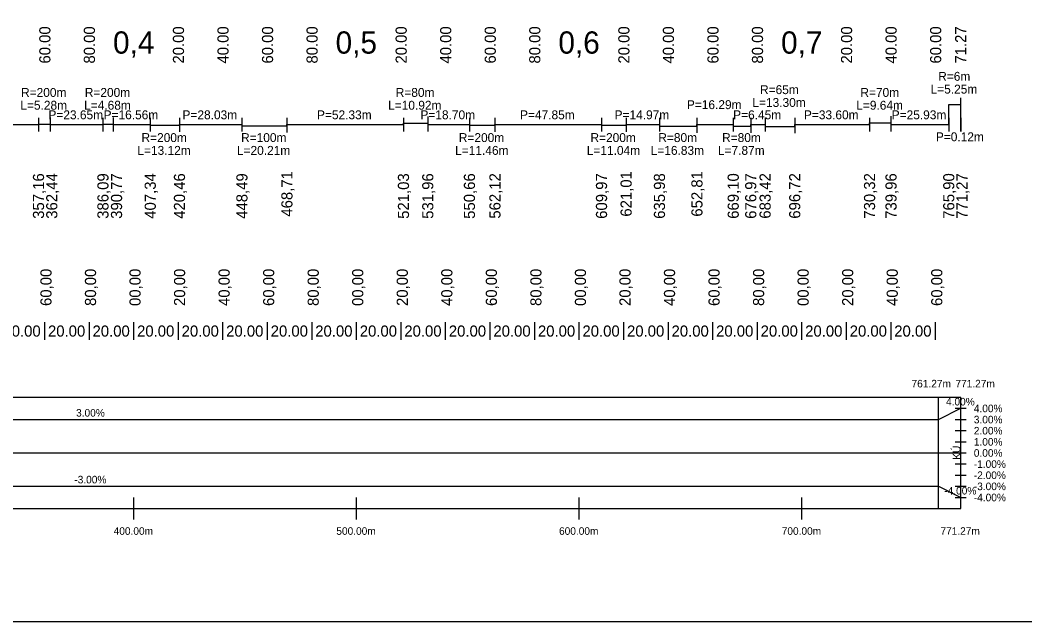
# Model space of a CAD drawing. Extents: x -603528 to -602138, y -1111983 to -1111218.
# Drawn here: x -603007.2 to -602556, y -1111982.7 to -1111712.4 of the extents above; entities that cross this region are included whole.
import ezdxf

# ---------------------------------------------------------------- set-up
doc = ezdxf.new("R2010")
doc.units = 0
for name, color, linetype in [('_křivky z hran', 7, 'Continuous'), ('_netisk', 7, 'Continuous'), ('C3D_Klopeni', 7, 'Continuous'), ('C3D_ZPP', 7, 'Continuous'), ('C3D_ZPP-Prouzky', 7, 'Continuous'), ('Default', 7, 'Continuous')]:
    doc.layers.add(name, color=color, linetype=linetype)

# ---------------------------------------------------------------- blocks, each defined once
blk = doc.blocks.new('AeccTickLine')
at = {"layer": 'Default'}
blk.add_line((0, 1), (0, -1), dxfattribs=at)

msp = doc.modelspace()

# ---------------------------------------------------------------- linework, layer by layer
at = {"layer": '_netisk'}
msp.add_lwpolyline([(-603527.56, -1111262.74), (-602137.56, -1111262.74), (-602137.56, -1111982.74), (-603527.56, -1111982.74)], close=True, dxfattribs=at)
at = {"layer": 'C3D_Klopeni'}
for p, q in [((-603356.07, -1111881.8), (-602584.81, -1111881.8)), ((-602594.8, -1111931.8), (-602594.8, -1111881.8)), ((-602584.81, -1111931.8), (-602584.81, -1111881.8)), ((-602584.81, -1111931.8), (-602584.81, -1111881.8)), ((-602594.8, -1111891.8), (-602584.81, -1111886.8)), ((-602587.31, -1111886.8), (-602582.31, -1111886.8)), ((-603356.07, -1111891.8), (-602594.8, -1111891.8)), ((-602587.31, -1111891.8), (-602582.31, -1111891.8)), ((-602587.31, -1111896.8), (-602582.31, -1111896.8)), ((-602587.31, -1111901.8), (-602582.31, -1111901.8)), ((-603356.07, -1111906.8), (-602584.81, -1111906.8)), ((-602587.31, -1111906.8), (-602582.31, -1111906.8)), ((-602587.31, -1111911.8), (-602582.31, -1111911.8)), ((-602587.31, -1111916.8), (-602582.31, -1111916.8)), ((-603356.07, -1111921.8), (-602594.8, -1111921.8)), ((-602594.8, -1111921.8), (-602584.81, -1111926.8)), ((-602587.31, -1111921.8), (-602582.31, -1111921.8)), ((-602956.07, -1111936.8), (-602956.07, -1111926.8)), ((-602856.07, -1111936.8), (-602856.07, -1111926.8)), ((-602756.07, -1111936.8), (-602756.07, -1111926.8)), ((-602656.07, -1111936.8), (-602656.07, -1111926.8)), ((-602587.31, -1111926.8), (-602582.31, -1111926.8)), ((-603356.07, -1111931.8), (-602584.81, -1111931.8))]:
    msp.add_line(p, q, dxfattribs=at)
at = {"layer": 'C3D_ZPP'}
for p, q in [((-602590.18, -1111759.4), (-602590.18, -1111750.4)), ((-602590.18, -1111750.4), (-602584.92, -1111750.4)), ((-602584.92, -1111750.4), (-602584.92, -1111759.4)), ((-603040.03, -1111759.4), (-602998.92, -1111759.4)), ((-602998.92, -1111759.4), (-602998.92, -1111759.13)), ((-602998.92, -1111759.13), (-602993.64, -1111759.13)), ((-602993.64, -1111759.13), (-602993.64, -1111759.4)), ((-602993.64, -1111759.4), (-602969.98, -1111759.4)), ((-602969.98, -1111759.4), (-602969.98, -1111759.13)), ((-602969.98, -1111759.13), (-602965.3, -1111759.13)), ((-602965.3, -1111759.13), (-602965.3, -1111759.4)), ((-602965.3, -1111759.4), (-602948.74, -1111759.4)), ((-602948.74, -1111759.4), (-602948.74, -1111759.67)), ((-602948.74, -1111759.67), (-602935.62, -1111759.67)), ((-602935.62, -1111759.67), (-602935.62, -1111759.4)), ((-602935.62, -1111759.4), (-602907.58, -1111759.4)), ((-602907.58, -1111759.4), (-602907.58, -1111759.94)), ((-602907.58, -1111759.94), (-602887.37, -1111759.94)), ((-602887.37, -1111759.94), (-602887.37, -1111759.4)), ((-602887.37, -1111759.4), (-602835.04, -1111759.4)), ((-602835.04, -1111759.4), (-602835.04, -1111758.72)), ((-602835.04, -1111758.72), (-602824.12, -1111758.72)), ((-602824.12, -1111758.72), (-602824.12, -1111759.4)), ((-602824.12, -1111759.4), (-602805.42, -1111759.4)), ((-602805.42, -1111759.4), (-602805.42, -1111759.67)), ((-602805.42, -1111759.67), (-602793.96, -1111759.67)), ((-602793.96, -1111759.67), (-602793.96, -1111759.4)), ((-602793.96, -1111759.4), (-602746.1, -1111759.4)), ((-602746.1, -1111759.4), (-602746.1, -1111759.67)), ((-602746.1, -1111759.67), (-602735.06, -1111759.67)), ((-602735.06, -1111759.67), (-602735.06, -1111759.4)), ((-602735.06, -1111759.4), (-602720.09, -1111759.4)), ((-602720.09, -1111759.4), (-602720.09, -1111760.07)), ((-602720.09, -1111760.07), (-602703.26, -1111760.07)), ((-602703.26, -1111760.07), (-602703.26, -1111759.4)), ((-602703.26, -1111759.4), (-602686.97, -1111759.4)), ((-602686.97, -1111759.4), (-602686.97, -1111760.07)), ((-602686.97, -1111760.07), (-602679.1, -1111760.07)), ((-602679.1, -1111760.07), (-602679.1, -1111759.4)), ((-602679.1, -1111759.4), (-602672.65, -1111759.4)), ((-602672.65, -1111759.4), (-602672.65, -1111760.23)), ((-602672.65, -1111760.23), (-602659.35, -1111760.23)), ((-602659.35, -1111760.23), (-602659.35, -1111759.4)), ((-602659.35, -1111759.4), (-602625.75, -1111759.4)), ((-602625.75, -1111759.4), (-602625.75, -1111758.62)), ((-602625.75, -1111758.62), (-602616.11, -1111758.62)), ((-602616.11, -1111758.62), (-602616.11, -1111759.4)), ((-602616.11, -1111759.4), (-602590.18, -1111759.4)), ((-602584.92, -1111759.4), (-602584.81, -1111759.4))]:
    msp.add_line(p, q, dxfattribs=at)
at = {"layer": 'C3D_ZPP-Prouzky'}
for p, q in [((-602996.07, -1111856.08), (-602996.07, -1111848.08)), ((-602976.07, -1111856.08), (-602976.07, -1111848.08)), ((-602956.07, -1111856.08), (-602956.07, -1111848.08)), ((-602936.07, -1111856.08), (-602936.07, -1111848.08)), ((-602916.07, -1111856.08), (-602916.07, -1111848.08)), ((-602896.07, -1111856.08), (-602896.07, -1111848.08)), ((-602876.07, -1111856.08), (-602876.07, -1111848.08)), ((-602856.07, -1111856.08), (-602856.07, -1111848.08)), ((-602836.07, -1111856.08), (-602836.07, -1111848.08)), ((-602816.07, -1111856.08), (-602816.07, -1111848.08)), ((-602796.07, -1111856.08), (-602796.07, -1111848.08)), ((-602776.07, -1111856.08), (-602776.07, -1111848.08)), ((-602756.07, -1111856.08), (-602756.07, -1111848.08)), ((-602736.07, -1111856.08), (-602736.07, -1111848.08)), ((-602716.07, -1111856.08), (-602716.07, -1111848.08)), ((-602696.07, -1111856.08), (-602696.07, -1111848.08)), ((-602676.07, -1111856.08), (-602676.07, -1111848.08)), ((-602656.07, -1111856.08), (-602656.07, -1111848.08)), ((-602636.07, -1111856.08), (-602636.07, -1111848.08)), ((-602616.07, -1111856.08), (-602616.07, -1111848.08)), ((-602596.07, -1111856.08), (-602596.07, -1111848.08))]:
    msp.add_line(p, q, dxfattribs=at)

# ---------------------------------------------------------------- block references
at = {"layer": '_křivky z hran', "xscale": 3, "yscale": 3}
for p in [(-602584.92, -1111750.4), (-602824.12, -1111758.72), (-602616.11, -1111758.62), (-602998.92, -1111759.4), (-602993.64, -1111759.13), (-602993.64, -1111759.4), (-602969.98, -1111759.4), (-602965.3, -1111759.13), (-602965.3, -1111759.4), (-602948.74, -1111759.4), (-602935.62, -1111759.4), (-602935.62, -1111759.67), (-602907.58, -1111759.4), (-602887.37, -1111759.4), (-602887.37, -1111759.94), (-602835.04, -1111759.4), (-602824.12, -1111759.4), (-602805.42, -1111759.4), (-602793.96, -1111759.4), (-602793.96, -1111759.67), (-602746.1, -1111759.4), (-602735.06, -1111759.4), (-602735.06, -1111759.67), (-602720.09, -1111759.4), (-602703.26, -1111759.4), (-602703.26, -1111760.07), (-602686.97, -1111759.4), (-602679.1, -1111759.4), (-602679.1, -1111760.07), (-602672.65, -1111759.4), (-602659.35, -1111759.4), (-602659.35, -1111760.23), (-602625.75, -1111759.4), (-602616.11, -1111759.4), (-602590.18, -1111759.4), (-602584.92, -1111759.4), (-602584.81, -1111759.4)]:
    msp.add_blockref('AeccTickLine', p, dxfattribs=at)

# ---------------------------------------------------------------- texts
at = {"layer": 'C3D_Klopeni'}
for s, p in [('761.27m', (-602606.87, -1111877.42)), ('771.27m', (-602587.16, -1111877.42)), ('771.27m', (-602587.16, -1111877.42)), ('4.00%', (-602591.39, -1111885.52)), ('4.00%', (-602578.91, -1111888.56)), ('3.00%', (-602982.02, -1111890.52)), ('3.00%', (-602578.91, -1111893.56)), ('2.00%', (-602578.91, -1111898.56)), ('1.00%', (-602578.91, -1111903.56)), ('0.00%', (-602578.91, -1111908.56)), ('0.00%', (-602578.91, -1111908.56)), ('-1.00%', (-602578.91, -1111913.56)), ('-3.00%', (-602982.81, -1111920.52)), ('-2.00%', (-602578.91, -1111918.56)), ('-4.00%', (-602592.18, -1111925.52)), ('-3.00%', (-602578.91, -1111923.56)), ('-4.00%', (-602578.91, -1111928.56)), ('400.00m', (-602965.16, -1111943.62)), ('500.00m', (-602865.16, -1111943.62)), ('600.00m', (-602765.16, -1111943.62)), ('700.00m', (-602665.16, -1111943.62)), ('771.27m', (-602593.9, -1111943.62))]:
    msp.add_text(s, height=3.4, dxfattribs=at).set_placement(p)
msp.add_text('KÚ', height=3.4, rotation=90, dxfattribs=at).set_placement((-602584.95, -1111909.91))
at = {"layer": 'C3D_ZPP-Prouzky'}
for s, p in [('60.00', (-602993.55, -1111731.96)), ('80.00', (-602973.55, -1111731.96)), ('20.00', (-602933.55, -1111731.96)), ('40.00', (-602913.55, -1111731.96)), ('60.00', (-602893.55, -1111731.96)), ('80.00', (-602873.55, -1111731.96)), ('20.00', (-602833.55, -1111731.96)), ('40.00', (-602813.55, -1111731.96)), ('60.00', (-602793.55, -1111731.96)), ('80.00', (-602773.55, -1111731.96)), ('20.00', (-602733.55, -1111731.96)), ('40.00', (-602713.55, -1111731.96)), ('60.00', (-602693.55, -1111731.96)), ('80.00', (-602673.55, -1111731.96)), ('20.00', (-602633.55, -1111731.96)), ('40.00', (-602613.55, -1111731.96)), ('60.00', (-602593.55, -1111731.96)), ('71.27', (-602582.29, -1111731.97)), ('357,16', (-602996.4, -1111801.69)), ('362,44', (-602990.44, -1111801.66)), ('386,09', (-602967.46, -1111801.69)), ('390,77', (-602961.36, -1111801.69)), ('407,34', (-602946.22, -1111801.66)), ('420,46', (-602933.1, -1111801.69)), ('448,49', (-602905.06, -1111801.69)), ('468,71', (-602884.85, -1111800.72)), ('521,03', (-602832.52, -1111801.69)), ('531,96', (-602821.6, -1111801.69)), ('550,66', (-602802.9, -1111801.69)), ('562,12', (-602791.44, -1111801.63)), ('609,97', (-602743.59, -1111801.69)), ('621,01', (-602732.54, -1111800.72)), ('635,98', (-602717.57, -1111801.69)), ('652,81', (-602700.74, -1111800.72)), ('669,10', (-602684.45, -1111801.67)), ('676,97', (-602676.58, -1111801.69)), ('683,42', (-602670.13, -1111801.63)), ('696,72', (-602656.83, -1111801.63)), ('730,32', (-602623.23, -1111801.63)), ('739,96', (-602613.59, -1111801.69)), ('765,90', (-602587.66, -1111801.67)), ('771,27', (-602581.74, -1111801.69)), ('60,00', (-602993.05, -1111840.84)), ('80,00', (-602973.05, -1111840.84)), ('00,00', (-602953.05, -1111840.84)), ('20,00', (-602933.05, -1111840.84)), ('40,00', (-602913.05, -1111840.84)), ('60,00', (-602893.05, -1111840.84)), ('80,00', (-602873.05, -1111840.84)), ('00,00', (-602853.05, -1111840.84)), ('20,00', (-602833.05, -1111840.84)), ('40,00', (-602813.05, -1111840.84)), ('60,00', (-602793.05, -1111840.84)), ('80,00', (-602773.05, -1111840.84)), ('00,00', (-602753.05, -1111840.84)), ('20,00', (-602733.05, -1111840.84)), ('40,00', (-602713.05, -1111840.84)), ('60,00', (-602693.05, -1111840.84)), ('80,00', (-602673.05, -1111840.84)), ('00,00', (-602653.05, -1111840.84)), ('20,00', (-602633.05, -1111840.84)), ('40,00', (-602613.05, -1111840.84)), ('60,00', (-602593.05, -1111840.84))]:
    msp.add_text(s, height=5, rotation=90, dxfattribs=at).set_placement(p)
for s, height, p in [('0,4', 10, (-602965.44, -1111727.51)), ('0,5', 10, (-602865.5, -1111727.51)), ('0,6', 10, (-602765.46, -1111727.51)), ('0,7', 10, (-602665.46, -1111727.51)), ('R=6m', 4, (-602594.9, -1111739.69)), ('R=65m', 4, (-602674.91, -1111745.68)), ('L=5.25m', 4, (-602598.32, -1111745.44)), ('R=200m', 4, (-603006.73, -1111746.93)), ('R=200m', 4, (-602978.1, -1111746.93)), ('R=80m', 4, (-602838.49, -1111746.93)), ('R=70m', 4, (-602629.84, -1111746.93)), ('L=5.28m', 4, (-603007.05, -1111752.68)), ('L=4.68m', 4, (-602978.41, -1111752.68)), ('L=10.92m', 4, (-602841.9, -1111752.68)), ('P=16.29m', 4, (-602707.75, -1111752.42)), ('L=13.30m', 4, (-602678.33, -1111751.43)), ('L=9.64m', 4, (-602631.7, -1111752.68)), ('P=23.65m', 4, (-602994.44, -1111756.98)), ('P=16.56m', 4, (-602969.66, -1111756.98)), ('P=28.03m', 4, (-602934.23, -1111756.98)), ('P=52.33m', 4, (-602873.84, -1111756.98)), ('P=18.70m', 4, (-602827.4, -1111756.98)), ('P=47.85m', 4, (-602782.66, -1111756.98)), ('P=14.97m', 4, (-602740.21, -1111756.98)), ('P=6.45m', 4, (-602686.96, -1111756.98)), ('P=33.60m', 4, (-602655.19, -1111756.98)), ('P=25.93m', 4, (-602615.78, -1111756.98)), ('R=200m', 4, (-602952.64, -1111767.21)), ('R=100m', 4, (-602907.93, -1111767.21)), ('R=200m', 4, (-602810.15, -1111767.21)), ('R=200m', 4, (-602751.04, -1111767.21)), ('R=80m', 4, (-602720.58, -1111767.21)), ('R=80m', 4, (-602691.94, -1111767.21)), ('P=0.12m', 4, (-602595.95, -1111766.85)), ('L=13.12m', 4, (-602954.5, -1111772.96)), ('L=20.21m', 4, (-602909.8, -1111772.96)), ('L=11.46m', 4, (-602811.8, -1111772.96)), ('L=11.04m', 4, (-602752.7, -1111772.96)), ('L=16.83m', 4, (-602724, -1111772.96)), ('L=7.87m', 4, (-602693.81, -1111772.96)), ('20.00', 5, (-603014.64, -1111854.6)), ('20.00', 5, (-602994.64, -1111854.6)), ('20.00', 5, (-602974.64, -1111854.6)), ('20.00', 5, (-602954.64, -1111854.6)), ('20.00', 5, (-602934.64, -1111854.6)), ('20.00', 5, (-602914.64, -1111854.6)), ('20.00', 5, (-602894.64, -1111854.6)), ('20.00', 5, (-602874.64, -1111854.6)), ('20.00', 5, (-602854.64, -1111854.6)), ('20.00', 5, (-602834.64, -1111854.6)), ('20.00', 5, (-602814.64, -1111854.6)), ('20.00', 5, (-602794.64, -1111854.6)), ('20.00', 5, (-602774.64, -1111854.6)), ('20.00', 5, (-602754.64, -1111854.6)), ('20.00', 5, (-602734.64, -1111854.6)), ('20.00', 5, (-602714.64, -1111854.6)), ('20.00', 5, (-602694.64, -1111854.6)), ('20.00', 5, (-602674.64, -1111854.6)), ('20.00', 5, (-602654.64, -1111854.6)), ('20.00', 5, (-602634.64, -1111854.6)), ('20.00', 5, (-602614.64, -1111854.6))]:
    msp.add_text(s, height=height, dxfattribs=at).set_placement(p)

doc.saveas('drawing.dxf')
